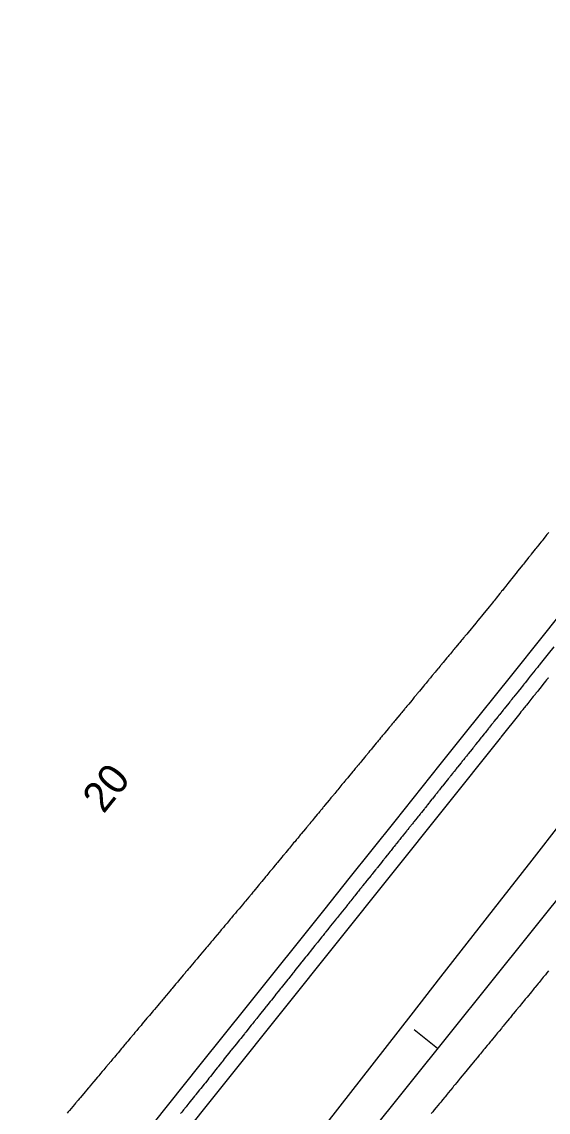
# Model space of a CAD drawing. Extents: x 2212475 to 2270595, y 470794 to 532458.
# Drawn here: x 2223848 to 2223987.7, y 472338.1 to 472627.4 of the extents above; entities that cross this region are included whole.
import ezdxf

# ---------------------------------------------------------------- set-up
doc = ezdxf.new("R2010")
doc.units = 0
for name, color, linetype in [('RD_DTM_Minor1', 7, 'Continuous'), ('RD_HC_Cl', 7, 'Continuous'), ('RD_HC_Data_Tic', 7, 'Continuous'), ('RD_HC_TX_Sta50', 7, 'Continuous')]:
    doc.layers.add(name, color=color, linetype=linetype)

msp = doc.modelspace()

# ---------------------------------------------------------------- linework, layer by layer
at = {"layer": 'RD_DTM_Minor1'}
for points in [[(2223882.82, 472335.05), (2223895.33, 472350.69), (2223907.85, 472366.34), (2223928.44, 472392.09), (2223934.84, 472400.09), (2223947.02, 472415.31), (2223959.03, 472430.33), (2223965.4, 472438.3), (2223977.98, 472454.03), (2223986.09, 472464.16), (2223998.58, 472479.78), (2224010.6, 472494.81), (2224023.09, 472510.42), (2224035.58, 472526.04), (2224060.56, 472557.28), (2224073.05, 472572.89), (2224096.89, 472602.7), (2224121.88, 472633.93), (2224134.37, 472649.55), (2224157.83, 472678.89), (2224174.97, 472700.31), (2224187.46, 472715.93), (2224210.92, 472745.26), (2224235.9, 472776.5)], [(2223926.16, 472331.71), (2223938.11, 472347.02), (2223951.3, 472363.92), (2223959.2, 472374.04), (2223974.75, 472393.96), (2223983.39, 472405.03), (2223998.81, 472424.78), (2224021.49, 472453.84), (2224033.81, 472469.63), (2224052.52, 472493.6), (2224058.27, 472500.97), (2224070.6, 472516.76), (2224083.84, 472533.73), (2224095.67, 472548.88), (2224108, 472564.68), (2224120.33, 472580.47), (2224145.21, 472612.34), (2224157.49, 472628.08), (2224180.72, 472657.84), (2224208.4, 472693.31), (2224220.7, 472709.07)], [(2223987.81, 472491.93), (2223987.34, 472491.35), (2223987.07, 472491.01), (2223986.32, 472490.07), (2223986.05, 472489.73), (2223985.8, 472489.43), (2223985.38, 472488.9), (2223984.88, 472488.28), (2223984.68, 472488.03), (2223984.46, 472487.75), (2223984.21, 472487.44), (2223983.19, 472486.17), (2223982.93, 472485.83), (2223982.68, 472485.52), (2223982.46, 472485.24), (2223982.26, 472484.99), (2223981.56, 472484.12), (2223981.34, 472483.84), (2223981.09, 472483.54), (2223980.82, 472483.2), (2223980.07, 472482.26), (2223979.56, 472481.62), (2223979.33, 472481.34), (2223979.14, 472481.09), (2223978.64, 472480.47), (2223978.44, 472480.22), (2223977.97, 472479.63), (2223977.7, 472479.29), (2223976.95, 472478.36), (2223976.68, 472478.02), (2223976.43, 472477.71), (2223976.01, 472477.18), (2223975.51, 472476.56), (2223975.32, 472476.31), (2223975.09, 472476.03), (2223974.85, 472475.73), (2223973.83, 472474.45), (2223973.56, 472474.11), (2223973.31, 472473.81), (2223973.09, 472473.53), (2223972.89, 472473.28), (2223972.02, 472472.19), (2223970.34, 472470.16), (2223969.95, 472469.69), (2223969.51, 472469.16), (2223969.01, 472468.56), (2223968.46, 472467.89), (2223966.41, 472465.42), (2223966.04, 472464.97), (2223965.81, 472464.7), (2223965.72, 472464.59), (2223965.67, 472464.53), (2223965.56, 472464.4), (2223965.45, 472464.26), (2223965.3, 472464.08), (2223964.85, 472463.54), (2223964.67, 472463.32), (2223964.21, 472462.76), (2223963.93, 472462.43), (2223963.15, 472461.49), (2223962.9, 472461.18), (2223962.71, 472460.95), (2223962.53, 472460.74), (2223962.48, 472460.68), (2223962.45, 472460.64), (2223962.38, 472460.55), (2223962.27, 472460.42), (2223961.71, 472459.75), (2223961.54, 472459.54), (2223961.33, 472459.29), (2223961.09, 472458.99), (2223960.81, 472458.66), (2223959.77, 472457.4), (2223959.57, 472457.17), (2223959.45, 472457.01), (2223959.39, 472456.94), (2223959.31, 472456.85), (2223959.2, 472456.71), (2223959.09, 472456.59), (2223958.96, 472456.43), (2223958.57, 472455.96), (2223958.41, 472455.76), (2223957.96, 472455.23), (2223957.69, 472454.89), (2223956.9, 472453.94), (2223956.64, 472453.62), (2223956.44, 472453.38), (2223956.24, 472453.14), (2223956.14, 472453.02), (2223956.09, 472452.96), (2223956.02, 472452.87), (2223955.92, 472452.75), (2223955.43, 472452.17), (2223955.27, 472451.98), (2223955.08, 472451.74), (2223954.84, 472451.46), (2223954.56, 472451.12), (2223953.5, 472449.84), (2223953.3, 472449.6), (2223953.16, 472449.43), (2223953.09, 472449.34), (2223952.97, 472449.19), (2223952.83, 472449.03), (2223952.74, 472448.92), (2223952.62, 472448.78), (2223952.29, 472448.37), (2223952.14, 472448.2), (2223951.72, 472447.68), (2223951.44, 472447.35), (2223950.64, 472446.39), (2223950.37, 472446.06), (2223950.16, 472445.81), (2223949.93, 472445.53), (2223949.79, 472445.36), (2223949.73, 472445.29), (2223949.65, 472445.19), (2223949.56, 472445.08), (2223949.14, 472444.58), (2223949.01, 472444.41), (2223948.82, 472444.19), (2223948.59, 472443.91), (2223948.31, 472443.58), (2223947.24, 472442.28), (2223947.03, 472442.02), (2223946.88, 472441.84), (2223946.78, 472441.73), (2223946.62, 472441.53), (2223946.47, 472441.36), (2223946.38, 472441.25), (2223946.28, 472441.13), (2223946, 472440.79), (2223945.87, 472440.63), (2223945.46, 472440.14), (2223945.18, 472439.8), (2223944.38, 472438.83), (2223944.1, 472438.5), (2223943.89, 472438.24), (2223943.63, 472437.93), (2223943.44, 472437.7), (2223943.37, 472437.61), (2223943.29, 472437.52), (2223943.2, 472437.41), (2223942.86, 472436.99), (2223942.73, 472436.84), (2223942.56, 472436.63), (2223942.33, 472436.36), (2223942.05, 472436.02), (2223940.97, 472434.71), (2223940.75, 472434.45), (2223940.58, 472434.25), (2223940.48, 472434.12), (2223940.27, 472433.87), (2223940.11, 472433.68), (2223940.03, 472433.58), (2223939.94, 472433.47), (2223939.71, 472433.19), (2223939.6, 472433.06), (2223939.2, 472432.58), (2223938.92, 472432.25), (2223938.11, 472431.26), (2223937.83, 472430.92), (2223937.61, 472430.65), (2223937.32, 472430.31), (2223937.09, 472430.04), (2223937.01, 472429.93), (2223936.93, 472429.84), (2223936.85, 472429.74), (2223936.56, 472429.4), (2223936.46, 472429.27), (2223936.29, 472429.07), (2223936.07, 472428.8), (2223935.79, 472428.47), (2223934.69, 472427.14), (2223934.46, 472426.86), (2223934.29, 472426.65), (2223934.17, 472426.51), (2223933.92, 472426.2), (2223933.75, 472425.99), (2223933.67, 472425.9), (2223933.6, 472425.82), (2223933.42, 472425.6), (2223933.32, 472425.48), (2223932.94, 472425.02), (2223932.66, 472424.69), (2223931.83, 472423.69), (2223931.55, 472423.35), (2223931.32, 472423.07), (2223931.01, 472422.7), (2223930.74, 472422.37), (2223930.65, 472422.26), (2223930.56, 472422.15), (2223930.49, 472422.06), (2223930.27, 472421.8), (2223930.18, 472421.69), (2223930.02, 472421.5), (2223929.81, 472421.24), (2223929.53, 472420.9), (2223928.41, 472419.56), (2223928.17, 472419.27), (2223927.99, 472419.05), (2223927.86, 472418.89), (2223927.57, 472418.54), (2223927.38, 472418.31), (2223927.31, 472418.23), (2223927.25, 472418.16), (2223927.12, 472418), (2223927.04, 472417.9), (2223926.67, 472417.46), (2223926.39, 472417.12), (2223925.56, 472416.11), (2223925.27, 472415.76), (2223925.03, 472415.47), (2223924.7, 472415.08), (2223924.39, 472414.71), (2223924.29, 472414.58), (2223924.2, 472414.47), (2223924.13, 472414.39), (2223923.97, 472414.2), (2223923.89, 472414.11), (2223923.75, 472413.93), (2223923.54, 472413.68), (2223923.26, 472413.34), (2223922.12, 472411.97), (2223921.88, 472411.68), (2223921.69, 472411.44), (2223921.54, 472411.27), (2223921.21, 472410.87), (2223921.02, 472410.63), (2223920.95, 472410.55), (2223920.91, 472410.5), (2223920.82, 472410.39), (2223920.75, 472410.31), (2223920.4, 472409.89), (2223920.12, 472409.55), (2223919.27, 472408.53), (2223918.98, 472408.17), (2223918.73, 472407.88), (2223918.38, 472407.45), (2223918.04, 472407.04), (2223917.92, 472406.9), (2223917.83, 472406.79), (2223917.77, 472406.71), (2223917.67, 472406.59), (2223917.61, 472406.52), (2223917.47, 472406.35), (2223917.26, 472406.1), (2223916.98, 472405.76), (2223915.83, 472404.38), (2223915.58, 472404.08), (2223915.38, 472403.83), (2223915.22, 472403.64), (2223914.86, 472403.2), (2223914.65, 472402.95), (2223914.59, 472402.87), (2223914.56, 472402.84), (2223914.52, 472402.79), (2223914.46, 472402.72), (2223914.12, 472402.31), (2223913.84, 472401.97), (2223912.99, 472400.94), (2223912.69, 472400.58), (2223912.43, 472400.27), (2223912.06, 472399.82), (2223911.68, 472399.37), (2223911.56, 472399.22), (2223911.47, 472399.11), (2223911.41, 472399.04), (2223911.36, 472398.98), (2223911.31, 472398.92), (2223911.19, 472398.77), (2223910.98, 472398.53), (2223910.7, 472398.18), (2223909.54, 472396.78), (2223909.28, 472396.47), (2223909.07, 472396.21), (2223908.9, 472396.01), (2223908.21, 472395.17), (2223907.3, 472394.1), (2223907.08, 472393.84), (2223906.82, 472393.53), (2223906.52, 472393.16), (2223905.64, 472392.12), (2223905.08, 472391.45), (2223904.86, 472391.19), (2223904.68, 472390.98), (2223904.28, 472390.5), (2223904.1, 472390.29), (2223903.62, 472389.72), (2223903.31, 472389.35), (2223902.43, 472388.3), (2223902.12, 472387.94), (2223901.86, 472387.63), (2223901.47, 472387.16), (2223901.07, 472386.69), (2223900.9, 472386.48), (2223900.68, 472386.22), (2223900.41, 472385.91), (2223899.22, 472384.48), (2223898.91, 472384.12), (2223898.64, 472383.8), (2223898.43, 472383.54), (2223898.26, 472383.34), (2223897.69, 472382.67), (2223897.48, 472382.41), (2223897.21, 472382.1), (2223896.9, 472381.73), (2223896, 472380.66), (2223895.43, 472379.98), (2223895.21, 472379.72), (2223895.04, 472379.52), (2223894.66, 472379.06), (2223894.49, 472378.86), (2223894.01, 472378.29), (2223893.69, 472377.92), (2223892.79, 472376.84), (2223892.48, 472376.47), (2223892.21, 472376.15), (2223891.83, 472375.7), (2223891.45, 472375.25), (2223891.29, 472375.06), (2223891.07, 472374.8), (2223890.8, 472374.48), (2223889.58, 472373.02), (2223889.26, 472372.65), (2223888.99, 472372.33), (2223888.78, 472372.07), (2223888.62, 472371.88), (2223888.08, 472371.25), (2223887.87, 472370.99), (2223887.6, 472370.67), (2223887.28, 472370.29), (2223886.36, 472369.2), (2223885.78, 472368.51), (2223885.56, 472368.25), (2223885.4, 472368.06), (2223885.04, 472367.63), (2223884.88, 472367.44), (2223884.4, 472366.86), (2223884.08, 472366.48), (2223883.15, 472365.38), (2223882.83, 472365), (2223882.56, 472364.68), (2223882.19, 472364.24), (2223881.84, 472363.82), (2223881.68, 472363.63), (2223881.46, 472363.37), (2223881.19, 472363.05), (2223879.94, 472361.56), (2223879.61, 472361.18), (2223879.35, 472360.86), (2223879.13, 472360.6), (2223878.98, 472360.42), (2223878.47, 472359.82), (2223878.26, 472359.57), (2223877.99, 472359.25), (2223877.66, 472358.86), (2223876.72, 472357.74), (2223876.13, 472357.03), (2223875.92, 472356.78), (2223875.76, 472356.6), (2223875.42, 472356.2), (2223875.27, 472356.01), (2223874.79, 472355.44), (2223874.46, 472355.05), (2223873.51, 472353.92), (2223873.18, 472353.53), (2223872.91, 472353.21), (2223872.55, 472352.78), (2223872.22, 472352.38), (2223872.07, 472352.2), (2223871.85, 472351.95), (2223871.58, 472351.63)], [(2223989.14, 472461.57), (2223987.62, 472459.68), (2223985.55, 472457.08), (2223985.33, 472456.82), (2223985.17, 472456.61), (2223984.79, 472456.13), (2223984.5, 472455.77), (2223984.46, 472455.73), (2223984.42, 472455.67), (2223984.4, 472455.65), (2223984.37, 472455.61), (2223984.35, 472455.58), (2223984.3, 472455.53), (2223984.18, 472455.38), (2223982.89, 472453.77), (2223982.61, 472453.41), (2223982.36, 472453.1), (2223982.16, 472452.85), (2223981.52, 472452.05), (2223981.43, 472451.93), (2223981.35, 472451.84), (2223981.31, 472451.78), (2223981.16, 472451.59), (2223981.13, 472451.56), (2223981.12, 472451.54), (2223981.08, 472451.49), (2223980.72, 472451.05), (2223980.46, 472450.73), (2223979.68, 472449.75), (2223979.41, 472449.41), (2223978.85, 472448.7), (2223978.51, 472448.28), (2223978.39, 472448.13), (2223978.29, 472448.01), (2223978.01, 472447.66), (2223977.96, 472447.6), (2223977.92, 472447.55), (2223977.89, 472447.51), (2223977.75, 472447.33), (2223977.63, 472447.19), (2223977.45, 472446.96), (2223977.21, 472446.66), (2223976, 472445.15), (2223975.83, 472444.93), (2223975.69, 472444.75), (2223975.37, 472444.36), (2223975.07, 472443.98), (2223974.99, 472443.89), (2223974.81, 472443.66), (2223974.74, 472443.58), (2223974.61, 472443.41), (2223974.53, 472443.31), (2223974.47, 472443.24), (2223974.36, 472443.09), (2223973.27, 472441.73), (2223973.03, 472441.43), (2223972.82, 472441.17), (2223972.66, 472440.96), (2223972.12, 472440.3), (2223972.02, 472440.17), (2223971.92, 472440.05), (2223971.83, 472439.94), (2223971.46, 472439.46), (2223971.4, 472439.4), (2223971.36, 472439.34), (2223971.26, 472439.22), (2223970.92, 472438.79), (2223970.7, 472438.52), (2223970.06, 472437.72), (2223969.83, 472437.43), (2223969.37, 472436.85), (2223969.09, 472436.51), (2223968.99, 472436.38), (2223968.88, 472436.25), (2223968.4, 472435.64), (2223968.3, 472435.52), (2223968.22, 472435.42), (2223968.16, 472435.34), (2223967.92, 472435.04), (2223967.81, 472434.9), (2223967.65, 472434.71), (2223967.45, 472434.45), (2223966.46, 472433.22), (2223966.32, 472433.04), (2223966.21, 472432.9), (2223965.95, 472432.58), (2223965.64, 472432.19), (2223965.52, 472432.04), (2223965.2, 472431.64), (2223965.08, 472431.5), (2223964.85, 472431.21), (2223964.71, 472431.03), (2223964.64, 472430.95), (2223964.53, 472430.81), (2223963.64, 472429.69), (2223963.45, 472429.45), (2223963.28, 472429.25), (2223963.15, 472429.08), (2223962.72, 472428.54), (2223962.61, 472428.41), (2223962.49, 472428.26), (2223962.36, 472428.09), (2223961.75, 472427.33), (2223961.67, 472427.22), (2223961.6, 472427.14), (2223961.44, 472426.94), (2223961.12, 472426.54), (2223960.94, 472426.32), (2223960.43, 472425.68), (2223960.26, 472425.46), (2223959.89, 472425), (2223959.68, 472424.74), (2223959.59, 472424.62), (2223959.48, 472424.49), (2223958.79, 472423.62), (2223958.64, 472423.44), (2223958.52, 472423.29), (2223958.42, 472423.16), (2223958.09, 472422.75), (2223957.98, 472422.62), (2223957.85, 472422.45), (2223957.69, 472422.25), (2223956.93, 472421.3), (2223956.82, 472421.16), (2223956.73, 472421.05), (2223956.54, 472420.81), (2223956.21, 472420.4), (2223956.04, 472420.2), (2223955.58, 472419.62), (2223955.42, 472419.41), (2223955.09, 472419), (2223954.89, 472418.76), (2223954.81, 472418.65), (2223954.71, 472418.52), (2223954.02, 472417.66), (2223953.87, 472417.48), (2223953.75, 472417.33), (2223953.65, 472417.2), (2223953.32, 472416.79), (2223953.21, 472416.65), (2223953.06, 472416.47), (2223952.89, 472416.25), (2223952.05, 472415.2), (2223951.93, 472415.05), (2223951.83, 472414.93), (2223951.62, 472414.66), (2223951.31, 472414.28), (2223951.18, 472414.12), (2223950.81, 472413.65), (2223950.68, 472413.49), (2223950.42, 472413.16), (2223950.26, 472412.97), (2223950.19, 472412.87), (2223950.07, 472412.73), (2223949.17, 472411.6), (2223948.98, 472411.36), (2223948.81, 472411.15), (2223948.68, 472410.99), (2223948.26, 472410.46), (2223948.16, 472410.33), (2223948.05, 472410.2), (2223947.93, 472410.05), (2223947.4, 472409.38), (2223947.32, 472409.28), (2223947.26, 472409.21), (2223947.12, 472409.04), (2223946.77, 472408.61), (2223946.57, 472408.35), (2223945.96, 472407.59), (2223945.75, 472407.33), (2223945.32, 472406.79), (2223945.07, 472406.48), (2223944.98, 472406.36), (2223944.88, 472406.24), (2223944.4, 472405.63), (2223944.3, 472405.51), (2223944.22, 472405.41), (2223944.15, 472405.33), (2223943.92, 472405.03), (2223943.8, 472404.89), (2223943.63, 472404.67), (2223943.41, 472404.4), (2223942.34, 472403.06), (2223942.18, 472402.87), (2223942.07, 472402.72), (2223941.8, 472402.39), (2223941.51, 472402.03), (2223941.42, 472401.92), (2223941.19, 472401.62), (2223941.11, 472401.52), (2223940.94, 472401.32), (2223940.85, 472401.2), (2223940.78, 472401.12), (2223940.66, 472400.97), (2223939.55, 472399.57), (2223939.31, 472399.27), (2223939.1, 472399.01), (2223938.94, 472398.81), (2223938.42, 472398.16), (2223938.33, 472398.05), (2223938.25, 472397.94), (2223938.17, 472397.85), (2223937.86, 472397.47), (2223937.82, 472397.41), (2223937.79, 472397.37), (2223937.71, 472397.27), (2223937.34, 472396.81), (2223937.09, 472396.5), (2223936.34, 472395.56), (2223936.08, 472395.24), (2223935.55, 472394.58), (2223935.25, 472394.2), (2223935.15, 472394.07), (2223935.06, 472393.95), (2223934.78, 472393.61), (2223934.73, 472393.55), (2223934.69, 472393.5), (2223934.66, 472393.45), (2223934.52, 472393.28), (2223934.39, 472393.12), (2223934.2, 472392.88), (2223933.93, 472392.55), (2223932.63, 472390.92), (2223932.44, 472390.68), (2223932.3, 472390.51), (2223931.98, 472390.11), (2223931.71, 472389.77), (2223931.67, 472389.72), (2223931.57, 472389.6), (2223931.54, 472389.56), (2223931.47, 472389.48), (2223931.44, 472389.43), (2223931.38, 472389.36), (2223931.26, 472389.2), (2223929.93, 472387.54), (2223929.64, 472387.18), (2223929.39, 472386.87), (2223929.19, 472386.62), (2223928.59, 472385.87), (2223928.5, 472385.76), (2223928.45, 472385.69), (2223928.41, 472385.65), (2223928.34, 472385.55), (2223928.33, 472385.54), (2223928.32, 472385.53), (2223928.3, 472385.51), (2223927.91, 472385.02), (2223927.62, 472384.65), (2223926.72, 472383.53), (2223926.41, 472383.15), (2223925.78, 472382.36), (2223925.16, 472381.58), (2223923.59, 472379.62), (2223923.28, 472379.24), (2223922.66, 472378.45), (2223922.3, 472378.01), (2223922.14, 472377.81), (2223921.93, 472377.55), (2223920.47, 472375.71), (2223920.16, 472375.32), (2223919.9, 472375), (2223919.69, 472374.74), (2223919.02, 472373.9), (2223918.81, 472373.64), (2223918.55, 472373.32), (2223918.24, 472372.93), (2223916.77, 472371.09), (2223916.56, 472370.83), (2223916.4, 472370.63), (2223916.05, 472370.2), (2223915.43, 472369.41), (2223915.11, 472369.02), (2223914.21, 472367.9), (2223913.9, 472367.51), (2223913.28, 472366.73), (2223912.93, 472366.29), (2223912.77, 472366.09), (2223912.56, 472365.83), (2223911.09, 472363.99), (2223910.78, 472363.6), (2223910.52, 472363.27), (2223910.31, 472363.01), (2223909.65, 472362.19), (2223909.44, 472361.93), (2223909.18, 472361.6), (2223908.87, 472361.21), (2223907.39, 472359.36), (2223907.18, 472359.1), (2223907.03, 472358.91), (2223906.68, 472358.48), (2223906.06, 472357.7), (2223905.74, 472357.3), (2223904.84, 472356.17), (2223904.52, 472355.78), (2223903.9, 472355), (2223903.56, 472354.57), (2223903.4, 472354.38), (2223903.19, 472354.12), (2223901.71, 472352.26), (2223901.4, 472351.87), (2223901.14, 472351.55), (2223900.93, 472351.29), (2223900.28, 472350.47), (2223900.07, 472350.21), (2223899.81, 472349.89), (2223899.49, 472349.49), (2223898.01, 472347.64), (2223897.8, 472347.38), (2223897.65, 472347.19), (2223897.31, 472346.76), (2223896.68, 472345.98), (2223896.37, 472345.59), (2223895.46, 472344.45), (2223895.15, 472344.06), (2223894.52, 472343.28), (2223894.18, 472342.85), (2223894.03, 472342.66), (2223893.82, 472342.4), (2223892.33, 472340.54), (2223892.02, 472340.15), (2223891.76, 472339.82), (2223891.55, 472339.56), (2223890.91, 472338.76), (2223890.7, 472338.5), (2223890.44, 472338.17), (2223890.12, 472337.77)], [(2223987.68, 472453.35), (2223987.65, 472453.3), (2223987.63, 472453.28), (2223987.61, 472453.26), (2223987.6, 472453.24), (2223987.57, 472453.21), (2223987.51, 472453.13), (2223987.49, 472453.1), (2223987.47, 472453.08), (2223987.46, 472453.07), (2223987.46, 472453.07), (2223987.46, 472453.07), (2223987.4, 472453), (2223987.24, 472452.79), (2223986.97, 472452.46), (2223986.59, 472451.99), (2223985.44, 472450.55), (2223985.06, 472450.07), (2223984.79, 472449.73), (2223984.62, 472449.52), (2223984.55, 472449.44), (2223984.52, 472449.4), (2223984.51, 472449.37), (2223984.48, 472449.34), (2223984.44, 472449.3), (2223984.4, 472449.25), (2223984.27, 472449.09), (2223984.23, 472449.03), (2223984.2, 472448.99), (2223984.18, 472448.97), (2223984.17, 472448.96), (2223984.17, 472448.96), (2223984.12, 472448.89), (2223983.97, 472448.7), (2223983.71, 472448.38), (2223983.35, 472447.93), (2223982.27, 472446.58), (2223981.91, 472446.13), (2223981.65, 472445.8), (2223981.49, 472445.6), (2223981.43, 472445.53), (2223981.4, 472445.49), (2223981.38, 472445.47), (2223981.34, 472445.42), (2223981.29, 472445.36), (2223981.23, 472445.28), (2223981.04, 472445.04), (2223980.98, 472444.96), (2223980.93, 472444.9), (2223980.9, 472444.87), (2223980.89, 472444.86), (2223980.89, 472444.85), (2223980.84, 472444.79), (2223980.69, 472444.61), (2223980.45, 472444.3), (2223980.11, 472443.88), (2223975.12, 472437.65), (2223975.07, 472437.58), (2223974.99, 472437.48), (2223974.89, 472437.35), (2223743.04, 472147.48)], [(2223987.76, 472375.61), (2223987.33, 472375.08), (2223987.14, 472374.86), (2223986.92, 472374.59), (2223986.37, 472373.92), (2223985.54, 472372.91), (2223985.24, 472372.55), (2223984.98, 472372.24), (2223984.76, 472371.97), (2223984.15, 472371.23), (2223983.97, 472371.01), (2223983.75, 472370.74), (2223983.49, 472370.43), (2223983.2, 472370.07), (2223982.06, 472368.69), (2223981.81, 472368.38), (2223981.59, 472368.11), (2223981.41, 472367.89), (2223980.98, 472367.37), (2223980.58, 472366.89), (2223980.32, 472366.57), (2223980.03, 472366.21), (2223979.18, 472365.19), (2223978.89, 472364.83), (2223978.41, 472364.25), (2223978.23, 472364.03), (2223977.81, 472363.52), (2223977.63, 472363.3), (2223977.41, 472363.03), (2223976.85, 472362.36), (2223976.01, 472361.33), (2223975.71, 472360.97), (2223975.45, 472360.66), (2223975.24, 472360.39), (2223974.63, 472359.66), (2223974.46, 472359.44), (2223974.24, 472359.18), (2223973.98, 472358.86), (2223973.68, 472358.5), (2223972.54, 472357.11), (2223972.28, 472356.8), (2223972.06, 472356.53), (2223971.88, 472356.32), (2223971.46, 472355.8), (2223971.06, 472355.32), (2223970.81, 472355.01), (2223970.51, 472354.65), (2223969.66, 472353.61), (2223969.36, 472353.25), (2223968.88, 472352.67), (2223968.71, 472352.46), (2223968.29, 472351.95), (2223968.11, 472351.73), (2223967.89, 472351.47), (2223967.34, 472350.79), (2223965.84, 472348.98), (2223964.35, 472347.16), (2223964.04, 472346.79), (2223963.79, 472346.48), (2223963.39, 472346), (2223962.98, 472345.5), (2223962.8, 472345.28), (2223962.58, 472345.02), (2223962.32, 472344.7), (2223961.16, 472343.29), (2223960.86, 472342.93), (2223960.6, 472342.61), (2223960.39, 472342.35), (2223960.21, 472342.13), (2223959.62, 472341.42), (2223959.4, 472341.15), (2223959.14, 472340.84), (2223958.84, 472340.47), (2223957.98, 472339.42), (2223957.42, 472338.74), (2223957.2, 472338.48), (2223957.03, 472338.27), (2223956.62, 472337.77)], [(2223871.58, 472351.63), (2223870.3, 472350.1), (2223869.97, 472349.71), (2223869.7, 472349.39), (2223869.49, 472349.14), (2223869.34, 472348.96), (2223868.86, 472348.39), (2223868.65, 472348.14), (2223868.38, 472347.82), (2223868.05, 472347.42), (2223867.08, 472346.28), (2223866.48, 472345.56), (2223866.27, 472345.31), (2223866.12, 472345.14), (2223865.81, 472344.76), (2223865.66, 472344.58), (2223865.18, 472344.01), (2223864.84, 472343.61), (2223863.87, 472342.46), (2223863.53, 472342.06), (2223863.26, 472341.74), (2223862.91, 472341.31), (2223862.6, 472340.95), (2223862.46, 472340.78), (2223862.25, 472340.53), (2223861.97, 472340.2), (2223860.65, 472338.64), (2223860.32, 472338.24), (2223860.05, 472337.91)]]:
    msp.add_lwpolyline(points, dxfattribs=at)
at = {"layer": 'RD_HC_Cl'}
msp.add_line((2222707.55, 470794.38), (2233931.89, 484799.33), dxfattribs=at)
at = {"layer": 'RD_HC_Data_Tic'}
msp.add_line((2223958.32, 472355.01), (2223952.08, 472360.01), dxfattribs=at)

# ---------------------------------------------------------------- texts
at = {"layer": 'RD_HC_TX_Sta50'}
msp.add_text('20', height=8, rotation=51.2894, dxfattribs=at).set_placement((2223869.68, 472417.1))

doc.saveas('drawing.dxf')
